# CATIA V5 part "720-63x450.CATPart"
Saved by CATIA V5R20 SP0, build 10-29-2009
Part number: 720-63x450
Definition: NONE
Nomenclature: 720-63x450
Source: Unknown
Description: 720-63x450
Bounding box of the stored display mesh (mm): x 0 to 450, y -31.5 to 31.5, z -31.5 to 31.5
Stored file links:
  C:\Users\Utente\Desktop\IO LAVORO\3D X SITO CF\X SITO\720\720-63x450.CATPart

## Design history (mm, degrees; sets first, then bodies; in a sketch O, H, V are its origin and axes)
Body1 "720-63x450" (main body)
  Solid1: solid without history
